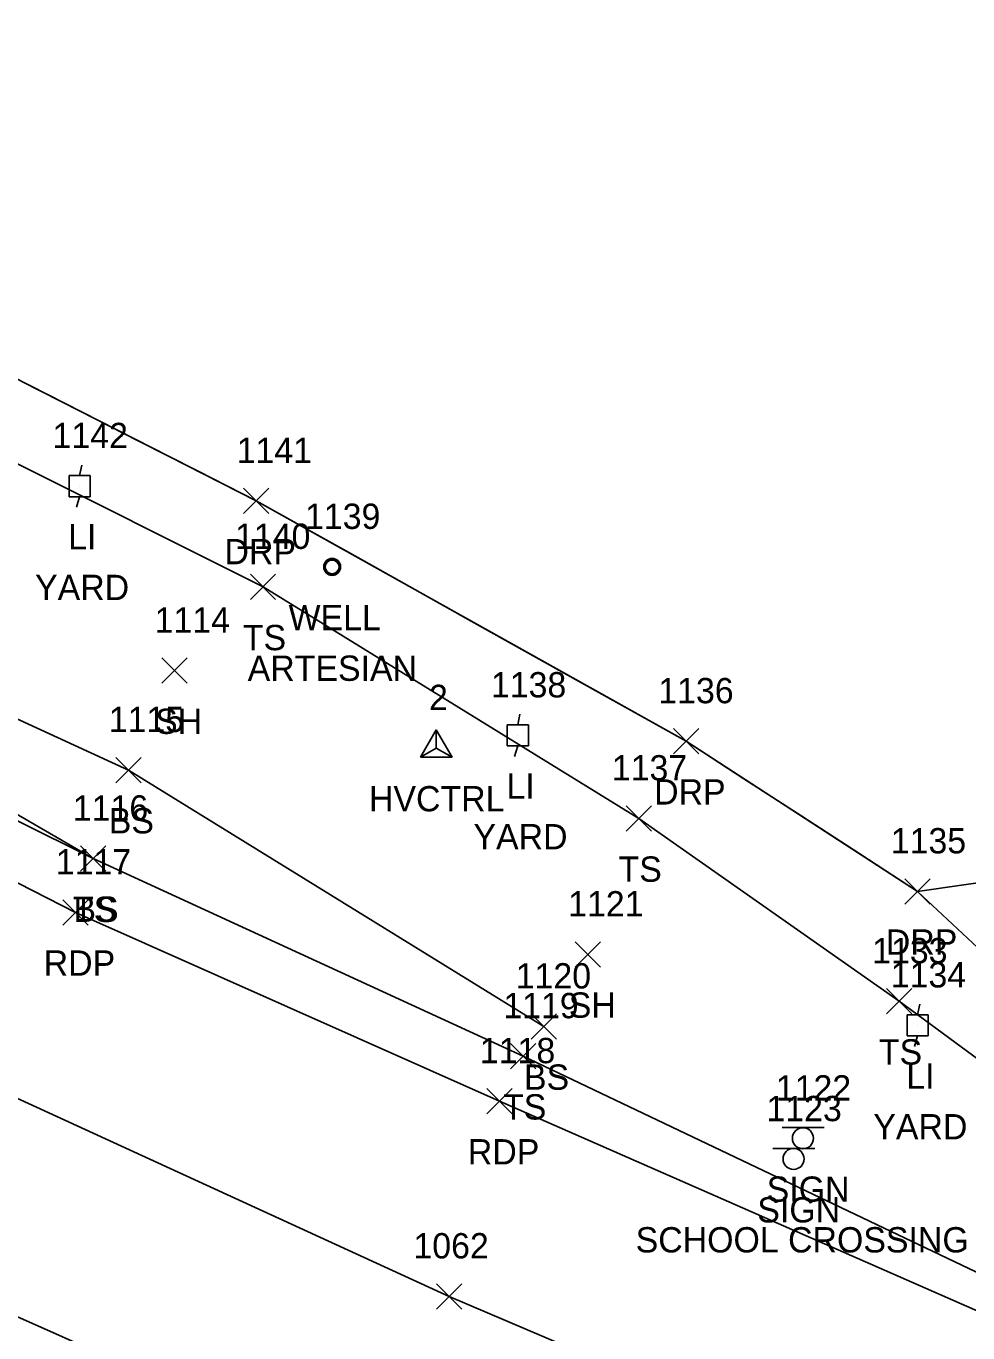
# Model space of a CAD drawing. Extents: x 1547013 to 1549434, y 267998 to 268739.
# Drawn here: x 1548393.1 to 1548467.5, y 268166.7 to 268269.9 of the extents above; entities that cross this region are included whole.
import ezdxf

# ---------------------------------------------------------------- set-up
doc = ezdxf.new("R2010")
doc.units = 0
for name, color, linetype in [('C_A', 7, 'Continuous'), ('C_I', 7, 'Continuous'), ('CPSM', 7, 'Continuous'), ('L_A', 7, 'Continuous'), ('L_I', 7, 'Continuous'), ('L_TIC', 7, 'Continuous'), ('LELB', 7, 'Continuous'), ('LSOGP', 7, 'Continuous'), ('P_A', 7, 'Continuous'), ('P_I', 7, 'Continuous'), ('P_TIC', 7, 'Continuous'), ('PET', 7, 'Continuous'), ('PRC', 7, 'Continuous'), ('R_A', 7, 'Continuous'), ('R_I', 7, 'Continuous'), ('R_TIC', 7, 'Continuous'), ('RDP', 7, 'Continuous'), ('S_A', 7, 'Continuous'), ('S_C', 7, 'Continuous'), ('S_I', 7, 'Continuous'), ('SSGN', 7, 'Continuous'), ('U_A', 7, 'Continuous'), ('U_C', 7, 'Continuous'), ('U_I', 7, 'Continuous'), ('ULP', 7, 'Continuous'), ('UWW', 7, 'Continuous')]:
    doc.layers.add(name, color=color, linetype=linetype)

msp = doc.modelspace()

# ---------------------------------------------------------------- linework, layer by layer
at = {"layer": 'CPSM'}
for p, q in [((1548424.27, 268212.18), (1548425.52, 268214.34)), ((1548424.27, 268212.18), (1548425.52, 268214.34)), ((1548426.77, 268212.18), (1548425.52, 268214.34)), ((1548425.52, 268212.9), (1548425.52, 268214.34)), ((1548426.77, 268212.18), (1548425.52, 268214.34)), ((1548425.52, 268212.9), (1548425.52, 268214.34)), ((1548424.27, 268212.18), (1548425.52, 268212.9)), ((1548424.27, 268212.18), (1548425.52, 268212.9)), ((1548424.27, 268212.18), (1548426.77, 268212.18)), ((1548424.27, 268212.18), (1548426.77, 268212.18)), ((1548425.52, 268212.9), (1548425.52, 268212.9)), ((1548425.52, 268212.9), (1548426.77, 268212.18)), ((1548425.52, 268212.9), (1548425.52, 268212.9)), ((1548425.52, 268212.9), (1548426.77, 268212.18))]:
    msp.add_line(p, q, dxfattribs=at)
at = {"layer": 'L_TIC'}
for points in [[(1548410.84, 268224.63), (1548412.84, 268226.63)], [(1548412.84, 268224.63), (1548410.84, 268226.63)], [(1548403.84, 268218.02), (1548405.84, 268220.02)], [(1548405.84, 268218.02), (1548403.84, 268220.02)], [(1548400.22, 268210.16), (1548402.22, 268212.16)], [(1548402.22, 268210.16), (1548400.22, 268212.16)], [(1548440.51, 268206.34), (1548442.51, 268208.34)], [(1548442.51, 268206.34), (1548440.51, 268208.34)], [(1548397.43, 268203.17), (1548399.43, 268205.17)], [(1548399.43, 268203.17), (1548397.43, 268205.17)], [(1548397.43, 268203.17), (1548399.43, 268205.17)], [(1548399.43, 268203.17), (1548397.43, 268205.17)], [(1548436.5, 268195.6), (1548438.5, 268197.6)], [(1548438.5, 268195.6), (1548436.5, 268197.6)], [(1548461.07, 268191.9), (1548463.07, 268193.9)], [(1548463.07, 268191.9), (1548461.07, 268193.9)], [(1548433.01, 268189.91), (1548435.01, 268191.91)], [(1548435.01, 268189.91), (1548433.01, 268191.91)], [(1548431.39, 268187.56), (1548433.39, 268189.56)], [(1548433.39, 268187.56), (1548431.39, 268189.56)]]:
    msp.add_lwpolyline(points, dxfattribs=at)
at = {"layer": 'LELB'}
for points in [[(1548296.73, 268261.5), (1548314.6, 268250.46), (1548321.28, 268249.75), (1548335.82, 268243.87), (1548371.49, 268224.82), (1548401.22, 268211.16), (1548434.01, 268190.91)], [(1548293.13, 268254.53), (1548332.25, 268235.07), (1548368.2, 268219.22), (1548398.43, 268204.17), (1548432.39, 268188.56), (1548470.91, 268170.21), (1548496.62, 268162.55), (1548482.16, 268178.12), (1548462.07, 268192.9), (1548441.51, 268207.34), (1548411.84, 268225.63), (1548370.54, 268246.3), (1548337.89, 268260.04)], [(1548295.23, 268257.98), (1548314.04, 268248.41), (1548316.67, 268246.8), (1548333.21, 268237.68), (1548369.42, 268221.01), (1548398.43, 268204.17)]]:
    msp.add_lwpolyline(points, dxfattribs=at)
at = {"layer": 'LSOGP'}
msp.add_lwpolyline([(1548480.17, 268203.98), (1548463.54, 268201.58), (1548458.97, 268204.55), (1548454.39, 268207.51), (1548449.82, 268210.47), (1548445.25, 268213.44), (1548436.76, 268218.18), (1548428.28, 268222.93), (1548419.8, 268227.68), (1548411.31, 268232.42), (1548406.67, 268234.79), (1548402.03, 268237.15), (1548397.39, 268239.51), (1548392.75, 268241.87)], dxfattribs=at)
at = {"layer": 'P_TIC'}
for points in [[(1548396.04, 268198.92), (1548398.04, 268200.92)], [(1548398.04, 268198.92), (1548396.04, 268200.92)], [(1548429.53, 268184.01), (1548431.53, 268186.01)], [(1548431.53, 268184.01), (1548429.53, 268186.01)], [(1548425.54, 268168.59), (1548427.54, 268170.59)], [(1548427.54, 268168.59), (1548425.54, 268170.59)]]:
    msp.add_lwpolyline(points, dxfattribs=at)
at = {"layer": 'PET'}
for points in [[(1548291.29, 268251.79), (1548331.75, 268232.06), (1548365.57, 268215.99), (1548397.04, 268199.92), (1548430.53, 268185.01), (1548469.56, 268167.88), (1548505.57, 268153.53), (1548548.45, 268139.73), (1548572.84, 268130.65), (1548596.65, 268123.57), (1548616.57, 268118.19), (1548655.34, 268109.04), (1548680.93, 268103.12), (1548700.8, 268099.76), (1548753.55, 268092.31), (1548788.11, 268088.53), (1548842.08, 268084.26), (1548868.98, 268083.24)], [(1548277.31, 268222.58), (1548324.08, 268200.05), (1548370.89, 268177.56), (1548421.34, 268155.12), (1548457.66, 268139.55), (1548491.25, 268126.1), (1548528.96, 268112.02), (1548568.2, 268099.41), (1548604.28, 268089.49), (1548621.9, 268083.87), (1548638.12, 268079.83), (1548660.94, 268075.04), (1548683.04, 268070.81), (1548718.59, 268065.27), (1548750.02, 268060.75), (1548786.09, 268057.26), (1548818, 268054.36), (1548866.14, 268051.84)]]:
    msp.add_lwpolyline(points, dxfattribs=at)
at = {"layer": 'PRC'}
msp.add_lwpolyline([(1548285.23, 268237.15), (1548330.43, 268214.75), (1548376.37, 268192.58), (1548426.54, 268169.59), (1548464.29, 268153.5), (1548497.35, 268140.09), (1548534.69, 268126.49), (1548572.93, 268114.69), (1548608.02, 268104.77), (1548637.81, 268097.38), (1548663.07, 268091.69), (1548686.38, 268086.96), (1548723.69, 268081.05), (1548751.9, 268076.9), (1548786.74, 268073.36), (1548818.76, 268070.54), (1548866.8, 268068.08)], dxfattribs=at)
at = {"layer": 'R_TIC'}
for points in [[(1548410.31, 268231.42), (1548412.31, 268233.42)], [(1548412.31, 268231.42), (1548410.31, 268233.42)], [(1548444.25, 268212.44), (1548446.25, 268214.44)], [(1548446.25, 268212.44), (1548444.25, 268214.44)], [(1548462.54, 268200.58), (1548464.54, 268202.58)], [(1548464.54, 268200.58), (1548462.54, 268202.58)]]:
    msp.add_lwpolyline(points, dxfattribs=at)
at = {"layer": 'RDP'}
msp.add_lwpolyline([(1548505.57, 268153.53), (1548507.08, 268156.6), (1548497.9, 268167.16), (1548485.25, 268181.3), (1548463.54, 268201.58), (1548445.25, 268213.44), (1548411.31, 268232.42), (1548374.18, 268251.32), (1548341.68, 268269.92)], dxfattribs=at)
at = {"layer": 'SSGN'}
for p, q in [((1548452.83, 268182.92), (1548456.17, 268182.92)), ((1548454.48, 268182.08), (1548454.48, 268182.08)), ((1548452.1, 268181.28), (1548455.43, 268181.28)), ((1548453.74, 268180.45), (1548453.74, 268180.45))]:
    msp.add_line(p, q, dxfattribs=at)
for centre in [(1548454.48, 268182.08), (1548453.74, 268180.45)]:
    msp.add_circle(centre, 0.833, dxfattribs=at)
at = {"layer": 'ULP'}
for p, q in [((1548397.52, 268235.25), (1548397.35, 268234.42)), ((1548396.52, 268232.75), (1548396.52, 268234.42)), ((1548396.52, 268234.42), (1548398.18, 268234.42)), ((1548398.18, 268234.42), (1548398.18, 268232.75)), ((1548398.18, 268232.75), (1548396.52, 268232.75)), ((1548397.1, 268231.92), (1548397.35, 268232.75)), ((1548397.35, 268233.59), (1548397.35, 268233.59)), ((1548432.13, 268215.57), (1548431.96, 268214.73)), ((1548431.13, 268213.07), (1548431.13, 268214.73)), ((1548431.13, 268214.73), (1548432.8, 268214.73)), ((1548432.8, 268214.73), (1548432.8, 268213.07)), ((1548432.8, 268213.07), (1548431.13, 268213.07)), ((1548431.71, 268212.23), (1548431.96, 268213.07)), ((1548431.96, 268213.9), (1548431.96, 268213.9)), ((1548463.71, 268192.66), (1548463.54, 268191.82)), ((1548462.71, 268190.16), (1548462.71, 268191.82)), ((1548462.71, 268191.82), (1548464.38, 268191.82)), ((1548464.38, 268191.82), (1548464.38, 268190.16)), ((1548463.54, 268190.99), (1548463.54, 268190.99)), ((1548464.38, 268190.16), (1548462.71, 268190.16)), ((1548463.29, 268189.32), (1548463.54, 268190.16))]:
    msp.add_line(p, q, dxfattribs=at)
at = {"layer": 'UWW'}
for radius in [0.667, 0.625, 0.583, 0.542]:
    msp.add_circle((1548417.3, 268227.21), radius, dxfattribs=at)

# ---------------------------------------------------------------- texts
at = {"layer": 'C_A'}
msp.add_text('HVCTRL', height=2, dxfattribs=at).set_placement((1548420.21, 268207.9))
msp.add_text('HVCTRL', height=2, dxfattribs=at).set_placement((1548420.21, 268207.9))
at = {"layer": 'C_I'}
msp.add_text('2', height=2, dxfattribs=at).set_placement((1548424.95, 268215.9))
msp.add_text('2', height=2, dxfattribs=at).set_placement((1548424.95, 268215.9))
at = {"layer": 'L_A'}
for s, p in [('TS', (1548410.25, 268220.63)), ('SH', (1548403.32, 268214.02)), ('BS', (1548399.66, 268206.16)), ('TS', (1548439.92, 268202.34)), ('TS', (1548396.84, 268199.17)), ('BS', (1548396.87, 268199.17)), ('SH', (1548435.99, 268191.6)), ('TS', (1548460.48, 268187.9)), ('BS', (1548432.45, 268185.91)), ('TS', (1548430.8, 268183.56))]:
    msp.add_text(s, height=2, dxfattribs=at).set_placement(p)
at = {"layer": 'L_I'}
for s, p in [('1140', (1548409.63, 268228.63)), ('1114', (1548403.28, 268222.02)), ('1115', (1548399.66, 268214.16)), ('1137', (1548439.39, 268210.34)), ('1116', (1548396.82, 268207.17)), ('1116', (1548396.82, 268207.17)), ('1121', (1548435.94, 268199.6)), ('1133', (1548459.95, 268195.9)), ('1120', (1548431.8, 268193.91)), ('1119', (1548430.82, 268191.56))]:
    msp.add_text(s, height=2, dxfattribs=at).set_placement(p)
at = {"layer": 'P_A'}
for p in [(1548394.52, 268194.92), (1548428.02, 268180.01)]:
    msp.add_text('RDP', height=2, dxfattribs=at).set_placement(p)
at = {"layer": 'P_I'}
for s, p in [('1117', (1548395.48, 268202.92)), ('1118', (1548428.97, 268188.01)), ('1062', (1548423.72, 268172.59))]:
    msp.add_text(s, height=2, dxfattribs=at).set_placement(p)
at = {"layer": 'R_A'}
for p in [(1548408.8, 268227.42), (1548442.73, 268208.44), (1548461.03, 268196.58)]:
    msp.add_text('DRP', height=2, dxfattribs=at).set_placement(p)
at = {"layer": 'R_I'}
for s, p in [('1141', (1548409.76, 268235.42)), ('1136', (1548443.06, 268216.44)), ('1135', (1548461.42, 268204.58))]:
    msp.add_text(s, height=2, dxfattribs=at).set_placement(p)
at = {"layer": 'S_A'}
for p in [(1548451.62, 268177.06), (1548450.88, 268175.43)]:
    msp.add_text('SIGN', height=2, dxfattribs=at).set_placement(p)
at = {"layer": 'S_C'}
msp.add_text('SCHOOL CROSSING', height=2, dxfattribs=at).set_placement((1548441.27, 268173.06))
at = {"layer": 'S_I'}
for s, p in [('1122', (1548452.34, 268185.06)), ('1123', (1548451.6, 268183.43))]:
    msp.add_text(s, height=2, dxfattribs=at).set_placement(p)
at = {"layer": 'U_A'}
for s, p in [('LI', (1548396.45, 268228.59)), ('WELL', (1548413.86, 268222.21)), ('LI', (1548431.07, 268208.9)), ('LI', (1548462.65, 268185.99))]:
    msp.add_text(s, height=2, dxfattribs=at).set_placement(p)
at = {"layer": 'U_C'}
for s, p in [('YARD', (1548393.84, 268224.59)), ('ARTESIAN', (1548410.63, 268218.21)), ('YARD', (1548428.46, 268204.9)), ('YARD', (1548460.04, 268181.99))]:
    msp.add_text(s, height=2, dxfattribs=at).set_placement(p)
at = {"layer": 'U_I'}
for s, p in [('1142', (1548395.22, 268236.59)), ('1139', (1548415.16, 268230.21)), ('1138', (1548429.84, 268216.9)), ('1134', (1548461.42, 268193.99))]:
    msp.add_text(s, height=2, dxfattribs=at).set_placement(p)

doc.saveas('drawing.dxf')
